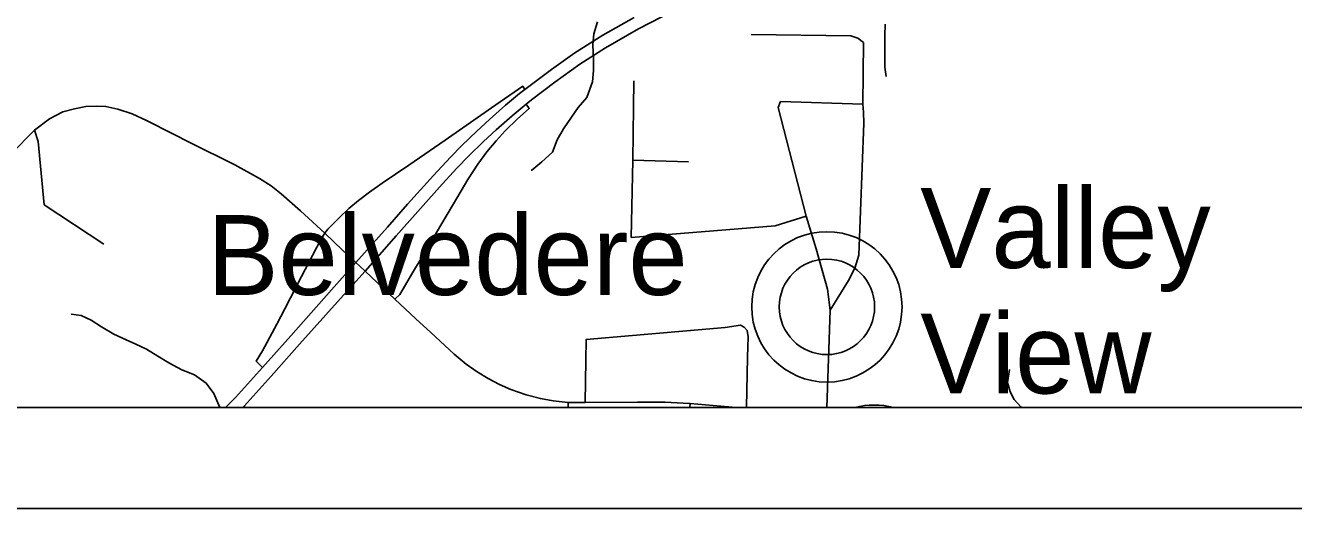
# Model space of a CAD drawing. Extents: x 0 to 34, y 0 to 22.
# Drawn here: x 3.211 to 4.467, y 14 to 14.478 of the extents above; entities that cross this region are included whole.
import ezdxf

# ---------------------------------------------------------------- set-up
doc = ezdxf.new("R2010")
doc.units = 0
for name, color, linetype in [('GM_X_Corporation', 7, 'Continuous'), ('GM_X_County_Road', 7, 'Continuous'), ('GM_X_Interchange_Ramps', 7, 'Continuous'), ('GM_X_Minor_River', 7, 'Continuous'), ('GM_X_State_Shield', 7, 'Continuous'), ('GM_X_Township_Road', 7, 'Continuous'), ('GM_X_Unincorporated', 7, 'Continuous'), ('GM_X_Unincorporated_Location', 7, 'Continuous'), ('GM_X_Unincorporated_Text', 7, 'Continuous'), ('GM_X_US_Route', 7, 'Continuous'), ('SH_Data', 7, 'Continuous')]:
    doc.layers.add(name, color=color, linetype=linetype)

msp = doc.modelspace()

# ---------------------------------------------------------------- linework, layer by layer
at = {"layer": 'GM_X_Corporation'}
msp.add_lwpolyline([(2.1, 15.7148), (2.1, 14.1), (4.5503, 14.1), (4.5507, 14.1138), (4.5505, 14.2449), (4.5614, 14.6695), (4.5616, 14.6767), (4.5617, 14.6817), (4.5685, 14.9157), (4.5738, 15.1325), (4.5873, 15.6794), (4.2138, 15.6834), (3.9277, 15.6898), (3.3171, 15.6975), (2.4078, 15.7088)], close=True, dxfattribs=at)
at = {"layer": 'GM_X_County_Road'}
for points in [[(3.1975, 14.3515), (3.2202, 14.3744), (3.2351, 14.3855), (3.2484, 14.3925), (3.2597, 14.3955), (3.2711, 14.3978), (3.2813, 14.3982), (3.2909, 14.3977), (3.3026, 14.3953), (3.3171, 14.3905), (3.3312, 14.3839), (3.3571, 14.3709)], [(3.3571, 14.3709), (3.3741, 14.3623), (3.4186, 14.3401), (3.443, 14.3267), (3.4546, 14.3192), (3.4646, 14.3114), (3.4835, 14.2946), (3.5076, 14.2725), (3.5253, 14.2557), (3.5384, 14.2435), (3.5426, 14.2396)], [(3.5426, 14.2396), (3.5475, 14.235), (3.5769, 14.2073), (3.5979, 14.1878), (3.6126, 14.1741), (3.6358, 14.1528), (3.6478, 14.1428), (3.6586, 14.1352), (3.6694, 14.1287), (3.6806, 14.1227), (3.6917, 14.1178), (3.707, 14.1125), (3.7211, 14.1089), (3.7339, 14.1067), (3.7487, 14.105), (3.7654, 14.105), (3.8173, 14.1054), (3.8445, 14.1052), (3.8684, 14.1041)], [(3.8684, 14.1041), (3.8693, 14.104), (3.9151, 14.1)]]:
    msp.add_lwpolyline(points, dxfattribs=at)
at = {"layer": 'GM_X_Interchange_Ramps'}
msp.add_line((3.4278, 14.1013), (3.429, 14.1), dxfattribs=at)
for points in [[(3.7056, 14.4147), (3.7037, 14.4178), (3.6728, 14.3965), (3.627, 14.3646), (3.5908, 14.3398), (3.5645, 14.3219), (3.5519, 14.3131), (3.5412, 14.3049), (3.5315, 14.2968), (3.5222, 14.288), (3.5107, 14.2764), (3.5076, 14.2725)], [(3.5769, 14.2073), (3.582, 14.212), (3.5945, 14.2333), (3.6049, 14.2507), (3.6225, 14.2806), (3.6351, 14.3017), (3.6493, 14.3256), (3.6592, 14.3409), (3.6682, 14.353), (3.6772, 14.364), (3.6863, 14.3737), (3.6984, 14.3857), (3.7101, 14.3959), (3.7072, 14.4003)], [(3.5076, 14.2725), (3.5042, 14.2668), (3.4955, 14.2503), (3.4847, 14.2296), (3.468, 14.1975), (3.4602, 14.1825), (3.4461, 14.1561), (3.4396, 14.1459), (3.446, 14.1395)]]:
    msp.add_lwpolyline(points, dxfattribs=at)
at = {"layer": 'GM_X_Minor_River'}
for points in [[(3.7776, 14.4815), (3.7739, 14.4697), (3.7729, 14.459), (3.7737, 14.4454), (3.7738, 14.4336), (3.7728, 14.4222), (3.7672, 14.4069), (3.7586, 14.397), (3.7518, 14.3874), (3.7439, 14.3756), (3.7376, 14.3649), (3.7331, 14.3527), (3.7226, 14.3431), (3.7128, 14.335), (3.712, 14.3347)], [(4.0626, 14.4792), (4.0623, 14.4682), (4.062, 14.4576), (4.0622, 14.4367), (4.0634, 14.4275)], [(3.4036, 14.1), (3.4028, 14.1023), (3.3978, 14.114), (3.3901, 14.1242), (3.3787, 14.1325), (3.3661, 14.1373), (3.3531, 14.1441), (3.3424, 14.1508), (3.3313, 14.1576), (3.3206, 14.1628), (3.3111, 14.1669), (3.2989, 14.1725), (3.2867, 14.18), (3.2764, 14.1864), (3.2665, 14.1912), (3.2566, 14.1923)]]:
    msp.add_lwpolyline(points, dxfattribs=at)
at = {"layer": 'GM_X_State_Shield'}
msp.add_line((4.0325, 14.1), (4.0706, 14.1), dxfattribs=at)
msp.add_arc((4.0516, 14.0281), 0.0744, 75.1445, 104.8555, dxfattribs=at)
at = {"layer": 'GM_X_Township_Road'}
for p, q in [((3.9589, 14.4028), (4.0405, 14.4)), ((3.8125, 14.3448), (3.8679, 14.3432)), ((3.7485, 14.1), (3.7487, 14.105)), ((3.8692, 14.1), (3.8693, 14.104))]:
    msp.add_line(p, q, dxfattribs=at)
for points in [[(3.9297, 14.4691), (4.0284, 14.4679), (4.0355, 14.4655), (4.041, 14.4613)], [(4.0409, 14.3921), (4.0405, 14.4), (4.041, 14.4613)], [(3.8136, 14.4232), (3.8125, 14.3448), (3.8111, 14.2684), (3.9537, 14.2797), (3.9843, 14.2895)], [(4.0081, 14.1964), (4.0055, 14.2171), (3.994, 14.2569), (3.9843, 14.2895), (3.9565, 14.397), (3.9589, 14.4028)], [(4.0046, 14.1), (4.0081, 14.1964), (4.0263, 14.2256), (4.0324, 14.238), (4.0364, 14.2508), (4.0413, 14.3812), (4.0409, 14.3921)], [(3.2202, 14.3744), (3.2239, 14.3631), (3.2299, 14.3007), (3.289, 14.2615)], [(3.7654, 14.105), (3.7665, 14.1674), (3.9041, 14.1793), (3.9194, 14.1814), (3.923, 14.1795), (3.926, 14.1761), (3.9267, 14.1699), (3.9262, 14.1497), (3.9251, 14.1)], [(4.1979, 14.1), (4.1967, 14.1008), (4.1903, 14.1078), (4.1864, 14.1157), (4.1835, 14.1249), (4.1855, 14.1378)]]:
    msp.add_lwpolyline(points, dxfattribs=at)
at = {"layer": 'GM_X_Unincorporated'}
for radius in [0.0744, 0.0472]:
    msp.add_circle((4.0048, 14.1996), radius, dxfattribs=at)
at = {"layer": 'GM_X_Unincorporated_Location'}
msp.add_line((4.0048, 14.1996), (4.0048, 14.1996), dxfattribs=at)
at = {"layer": 'GM_X_US_Route'}
for points in [[(3.4265, 14.1), (3.4278, 14.1013), (3.4546, 14.1309), (3.4827, 14.1626), (3.5232, 14.2079), (3.5475, 14.235), (3.5782, 14.2698), (3.6238, 14.321), (3.6386, 14.3373), (3.6501, 14.3487), (3.6647, 14.3631), (3.6772, 14.3746), (3.6932, 14.3886), (3.7072, 14.4003), (3.7122, 14.4043), (3.7353, 14.422), (3.7602, 14.4396), (3.7856, 14.4558), (3.8183, 14.4747), (3.8521, 14.4921)], [(3.4095, 14.1), (3.4192, 14.1099), (3.446, 14.1395), (3.4741, 14.1711), (3.5144, 14.2164), (3.5384, 14.2435), (3.5696, 14.2785), (3.5897, 14.3011), (3.6152, 14.3297), (3.632, 14.3477), (3.6435, 14.3591), (3.6581, 14.3736), (3.6706, 14.385), (3.6867, 14.399), (3.7006, 14.4107), (3.7056, 14.4147), (3.7322, 14.4346), (3.7553, 14.4508), (3.783, 14.4683), (3.8139, 14.4859)]]:
    msp.add_lwpolyline(points, dxfattribs=at)
at = {"layer": 'SH_Data'}
msp.add_line((2, 14), (9, 14), dxfattribs=at)
msp.add_lwpolyline([(2.1, 20.9), (8.9, 20.9), (8.9, 14.1), (2.1, 14.1)], close=True, dxfattribs=at)

# ---------------------------------------------------------------- texts
at = {"layer": 'GM_X_Unincorporated_Text'}
for s, p in [('Valley', (4.0972, 14.2381)), ('Belvedere', (3.3914, 14.2114)), ('View', (4.0972, 14.1139))]:
    msp.add_text(s, height=0.07898, rotation=0, dxfattribs=at).set_placement(p)

doc.saveas('drawing.dxf')
